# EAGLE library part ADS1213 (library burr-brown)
22-Bit Analog-to-Digital Converter
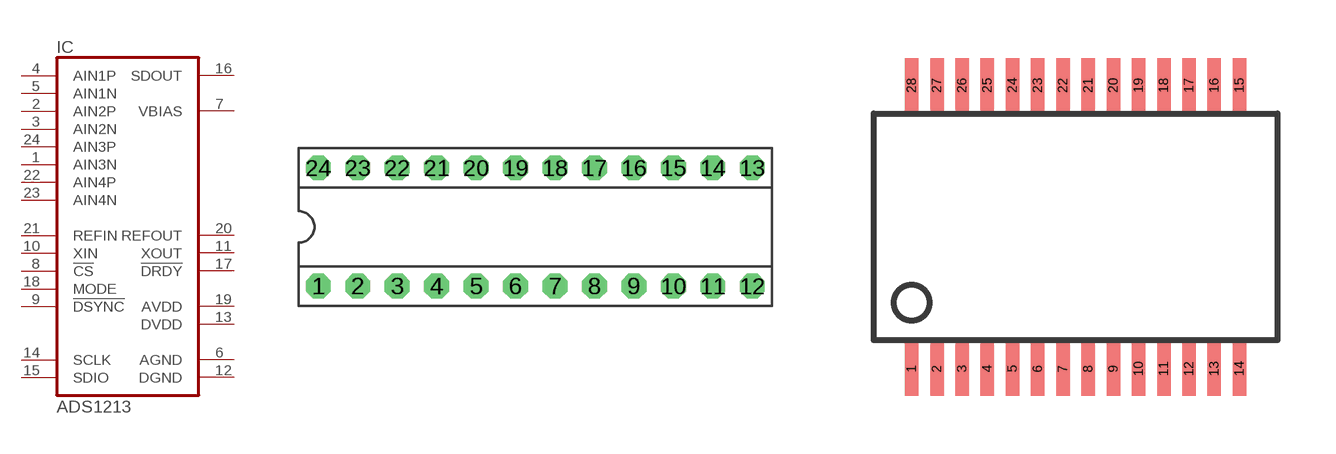
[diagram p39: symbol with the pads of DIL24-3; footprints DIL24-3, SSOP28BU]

Designator prefix IC

## ADS1213P (MF: TEXAS INSTRUMENTS; MPN: ADS1213P; OC_FARNELL: unknown; OC_NEWARK: 14M9330)  [DIL24-3]
1  AIN3N  in
2  AIN2P  in
3  AIN2N  in
4  AIN1P  in
5  AIN1N  in
6  AGND  pwr
7  VBIAS  out
8  !CS  in
9  !DSYNC  in
10  XIN  in
11  XOUT  out
12  DGND  pwr
13  DVDD  pwr
14  SCLK
15  SDIO
16  SDOUT  out
17  !DRDY  out
18  MODE  in
19  AVDD  pwr
20  REFOUT  out
21  REFIN  in
22  AIN4P  in
23  AIN4N  in
24  AIN3P  in

## ADS1213E (MF: TEXAS INSTRUMENTS; MPN: ADS1213E; OC_FARNELL: unknown; OC_NEWARK: 74C6980)  [SSOP28BU]
1  AIN3N  in
2  AIN2P  in
3  AIN2N  in
4  AIN1P  in
5  AIN1N  in
6  AGND  pwr
7  VBIAS  out
10  !CS  in
11  !DSYNC  in
12  XIN  in
13  XOUT  out
14  DGND  pwr
15  DVDD  pwr
16  SCLK
17  SDIO
18  SDOUT  out
19  !DRDY  out
22  MODE  in
23  AVDD  pwr
24  REFOUT  out
25  REFIN  in
26  AIN4P  in
27  AIN4N  in
28  AIN3P  in

## ADS1213U (MF: TEXAS INSTRUMENTS; MPN: ADS1213U; OC_FARNELL: 1234905; OC_NEWARK: 35C1517)  [SO24L]
Pads as for DIL24-3

## Footprint DIL24-3 (pad centres in mm)
Dual In Line 0.3 inch
drill 0.813 pad 1.6 octagon: 1 -13.97,-3.81; 2 -11.43,-3.81; 3 -8.89,-3.81; 4 -6.35,-3.81; 5 -3.81,-3.81; 6 -1.27,-3.81; 7 1.27,-3.81; 8 3.81,-3.81; 9 6.35,-3.81; 10 8.89,-3.81; 11 11.43,-3.81; 12 13.97,-3.81; 13 13.97,3.81; 14 11.43,3.81; 15 8.89,3.81; 16 6.35,3.81; 17 3.81,3.81; 18 1.27,3.81; 19 -1.27,3.81; 20 -3.81,3.81; 21 -6.35,3.81; 22 -8.89,3.81; 23 -11.43,3.81; 24 -13.97,3.81

## Footprint SSOP28BU (pad centres in mm)
Small Shrink Outline Package
smd 0.348 x 1.397: 1 -4.225,-3.656; 2 -3.575,-3.656; 3 -2.925,-3.656; 4 -2.275,-3.656; 5 -1.625,-3.656; 6 -0.975,-3.656; 7 -0.325,-3.656; 8 0.325,-3.656; 9 0.975,-3.656; 10 1.625,-3.656; 11 2.275,-3.656; 12 2.925,-3.656; 13 3.575,-3.656; 14 4.225,-3.656; 15 4.225,3.656; 16 3.575,3.656; 17 2.925,3.656; 18 2.275,3.656; 19 1.625,3.656; 20 0.975,3.656; 21 0.325,3.656; 22 -0.325,3.656; 23 -0.975,3.656; 24 -1.625,3.656; 25 -2.275,3.656; 26 -2.925,3.656; 27 -3.575,3.656; 28 -4.225,3.656

## Footprint SO24L (pad centres in mm)
Small Outline Package, large
smd 0.61 x 2.21: 1 -6.985,-5.029; 2 -5.715,-5.029; 3 -4.445,-5.029; 4 -3.175,-5.029; 5 -1.905,-5.029; 6 -0.635,-5.029; 7 0.635,-5.029; 8 1.905,-5.029; 9 3.175,-5.029; 10 4.445,-5.029; 11 5.715,-5.029; 12 6.985,-5.029; 13 6.985,5.029; 14 5.715,5.029; 15 4.445,5.029; 16 3.175,5.029; 17 1.905,5.029; 18 0.635,5.029; 19 -0.635,5.029; 20 -1.905,5.029; 21 -3.175,5.029; 22 -4.445,5.029; 23 -5.715,5.029; 24 -6.985,5.029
